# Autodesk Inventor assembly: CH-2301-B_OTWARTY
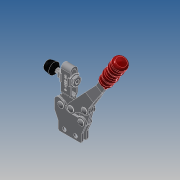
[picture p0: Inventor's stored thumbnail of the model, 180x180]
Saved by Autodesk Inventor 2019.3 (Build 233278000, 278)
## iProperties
Company: Î¢ÈíÖÐ¹ú
Created: 2012-09
Part Number: CH-2301-B_OTWARTY
Material: Ogólny
Description: STEP AP203
Document SubType Name: Assembly
Designer: CADENGINEERING4
Sending System: SolidWorks 2010
Preprocessor: SwSTEP 2.0
Title: CH-2301-B.STEP
Author: Î¢ÈíÓÃ»§
Revision Number: ÈÎºÎ
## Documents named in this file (10)
- E:\STRONA\Horizontal toggle clamp\CH-2301-B\CH-2301-B_OTWARTY.iam
- E:\STRONA\Horizontal toggle clamp\CH-2301-B\CH-2301-B-02___.ipt
- E:\STRONA\Horizontal toggle clamp\CH-2301-B\CH-2300-05____1.ipt
- E:\STRONA\Horizontal toggle clamp\CH-2301-B\FW100____1.ipt
- E:\STRONA\Horizontal toggle clamp\CH-2301-B\CH-2301-B-01___.ipt
- E:\STRONA\Horizontal toggle clamp\CH-2301-B\CH-2300-06___.ipt
- E:\STRONA\Horizontal toggle clamp\CH-2301-B\CH-FC-10138____1.ipt
- E:\STRONA\Horizontal toggle clamp\CH-2301-B\CH-2300-03____1.ipt
- E:\STRONA\Horizontal toggle clamp\CH-2301-B\10138-02____1.ipt
- E:\STRONA\Horizontal toggle clamp\CH-2301-B\CH-2300-04____1.ipt
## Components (14 placed, 14 different names)
1. CH-2301-B-02____1 — Zestawiające:1, Kątowe:1, Zestawiające:20, Zestawiające:21, Zestawiające:22, Zestawiające:23, Zestawiające:24, Zestawiające:25, Zestawiające:29
2. CH-2300-05____1_2 — Zestawiające:23, Zestawiające:26
3. CH-2300-05____1_3 — Zestawiające:12, Zestawiające:13
4. FW100____1_4 — Zestawiające:2, Równoległe:1, Zestawiające:17, Zestawiające:18, Zestawiające:20
5. FW100____1_5 — Równoległe:1, Zestawiające:14, Zestawiające:16, Zestawiające:21
6. CH-2301-B-01____6 — Zestawiające:6, Zestawiające:7, Zestawiające:8, Zestawiające:9, Zestawiające:24, Zestawiające:25, Zestawiające:26, Przejściowe:1
7. CH-2300-05____1_7 — Zestawiające:27, Zestawiające:28, Zestawiające:29
8. CH-2300-06____8 — Zestawiające:3, Zestawiające:4, Zestawiające:5
9. CH-FC-10138____1_9 — Równoległe:2, Zestawiające:14, Zestawiające:15, Zestawiające:17, Zestawiające:19, Zestawiające:22
10. CH-2300-05____1_10 — Zestawiające:8, Zestawiające:9
11. CH-2300-03____1_11 — Zestawiające:3, Zestawiające:4, Zestawiające:5, Zestawiające:10, Zestawiające:11, Zestawiające:12, Zestawiające:13, Zestawiające:27, Zestawiające:28, Przejściowe:1
12. 10138-02____1_12 — Równoległe:2, Zestawiające:18, Zestawiające:19
13. CH-2300-04____1_13 — Zestawiające:6, Zestawiające:7, Zestawiające:10, Zestawiające:11
14. 10138-02____1_14 — Zestawiające:15, Zestawiające:16
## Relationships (33: Mate 29, Flush 2, Angle 1, Transitional 1)
- Zestawiające:1 [Mate]: CH-2301-B-02____1
- Kątowe:1 [Angle]: CH-2301-B-02____1
- Zestawiające:2 [Mate]: FW100____1_4
- Równoległe:1 [Flush]: FW100____1_4 ↔ FW100____1_5
- Równoległe:2 [Flush]: CH-FC-10138____1_9 ↔ 10138-02____1_12
- Zestawiające:3 [Mate]: CH-2300-06____8 ↔ CH-2300-03____1_11
- Zestawiające:4 [Mate]: CH-2300-06____8 ↔ CH-2300-03____1_11
- Zestawiające:5 [Mate]: CH-2300-06____8 ↔ CH-2300-03____1_11
- Zestawiające:6 [Mate]: CH-2301-B-01____6 ↔ CH-2300-04____1_13
- Zestawiające:7 [Mate]: CH-2301-B-01____6 ↔ CH-2300-04____1_13
- Zestawiające:8 [Mate]: CH-2301-B-01____6 ↔ CH-2300-05____1_10
- Zestawiające:9 [Mate]: CH-2301-B-01____6 ↔ CH-2300-05____1_10
- Zestawiające:10 [Mate]: CH-2300-03____1_11 ↔ CH-2300-04____1_13
- Zestawiające:11 [Mate]: CH-2300-03____1_11 ↔ CH-2300-04____1_13
- Zestawiające:12 [Mate]: CH-2300-05____1_3 ↔ CH-2300-03____1_11
- Zestawiające:13 [Mate]: CH-2300-05____1_3 ↔ CH-2300-03____1_11
- Zestawiające:14 [Mate]: FW100____1_5 ↔ CH-FC-10138____1_9
- Zestawiające:15 [Mate]: CH-FC-10138____1_9 ↔ 10138-02____1_14
- Zestawiające:16 [Mate]: FW100____1_5 ↔ 10138-02____1_14
- Zestawiające:17 [Mate]: FW100____1_4 ↔ CH-FC-10138____1_9
- Zestawiające:18 [Mate]: FW100____1_4 ↔ 10138-02____1_12
- Zestawiające:19 [Mate]: CH-FC-10138____1_9 ↔ 10138-02____1_12
- Zestawiające:20 [Mate]: CH-2301-B-02____1 ↔ FW100____1_4
- Zestawiające:21 [Mate]: CH-2301-B-02____1 ↔ FW100____1_5
- Zestawiające:22 [Mate]: CH-2301-B-02____1 ↔ CH-FC-10138____1_9
- Zestawiające:23 [Mate]: CH-2301-B-02____1 ↔ CH-2300-05____1_2
- Zestawiające:24 [Mate]: CH-2301-B-02____1 ↔ CH-2301-B-01____6
- Zestawiające:25 [Mate]: CH-2301-B-02____1 ↔ CH-2301-B-01____6
- Zestawiające:26 [Mate]: CH-2300-05____1_2 ↔ CH-2301-B-01____6
- Zestawiające:27 [Mate]: CH-2300-05____1_7 ↔ CH-2300-03____1_11
- Zestawiające:28 [Mate]: CH-2300-05____1_7 ↔ CH-2300-03____1_11
- Zestawiające:29 [Mate]: CH-2301-B-02____1 ↔ CH-2300-05____1_7
- Przejściowe:1 [Transitional]: CH-2301-B-01____6 ↔ CH-2300-03____1_11
